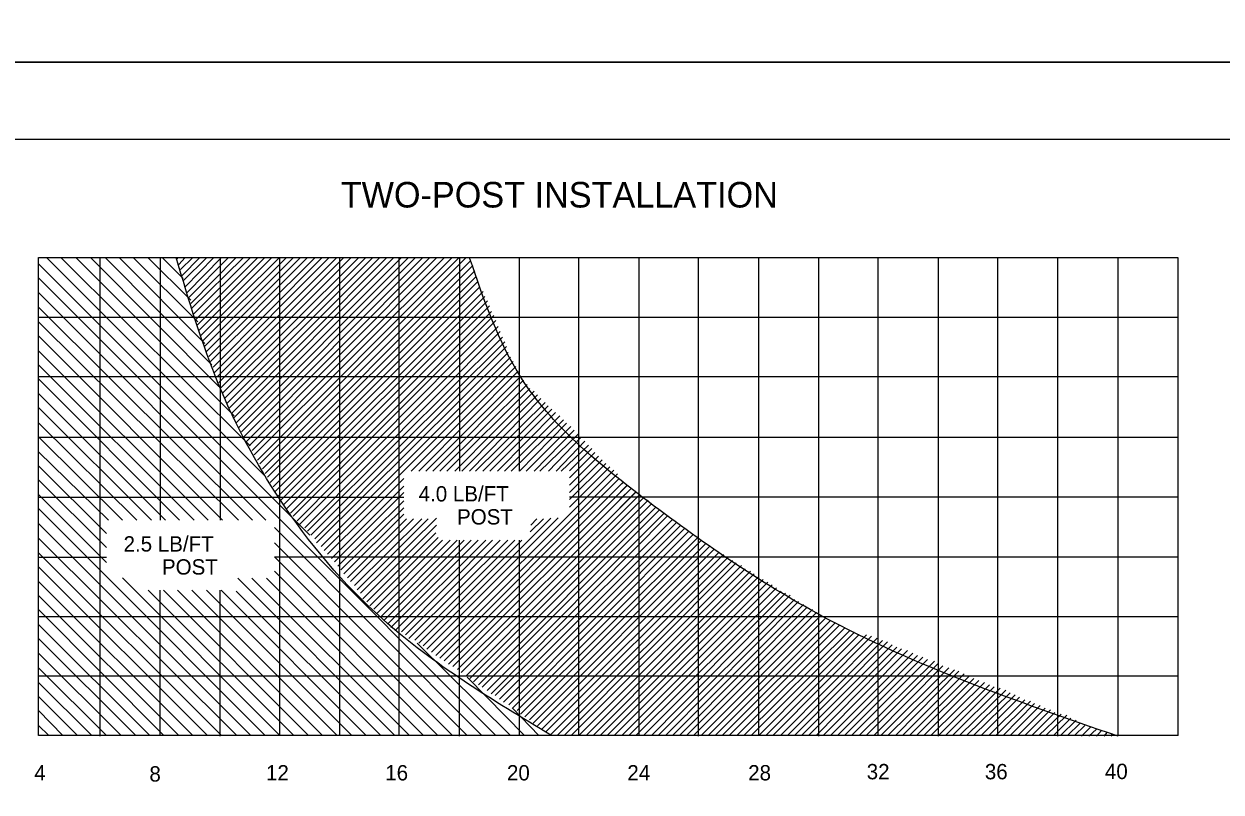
# Model space of a CAD drawing. Extents: x 644358 to 648627, y 294594 to 295782.
# Drawn here: x 645520.7 to 645754.7, y 295045 to 295195.1 of the extents above; entities that cross this region are included whole.
import ezdxf

# ---------------------------------------------------------------- set-up
doc = ezdxf.new("R2010")
doc.units = 0
for name, color, linetype in [('1', 7, 'Continuous'), ('10', 7, 'Continuous'), ('2', 7, 'Continuous'), ('4', 7, 'Continuous'), ('PLT-BNDY', 7, 'Continuous')]:
    doc.layers.add(name, color=color, linetype=linetype)

msp = doc.modelspace()

# ---------------------------------------------------------------- linework, layer by layer
at = {"layer": '1'}
msp.add_line((645239.31, 295172.63), (646025.31, 295172.63), dxfattribs=at)
at = {"layer": '10'}
for p, q in [((645576.63, 295095.21), (645523.59, 295148.25)), ((645567.96, 295106.63), (645525.21, 295149.38)), ((645564.96, 295112.63), (645527.96, 295149.38)), ((645561.84, 295118.5), (645530.84, 295149.5)), ((645558.84, 295124.25), (645533.71, 295149.5)), ((645557.46, 295128.5), (645536.59, 295149.5)), ((645556.09, 295132.63), (645539.34, 295149.5)), ((645554.71, 295136.88), (645542.09, 295149.5)), ((645553.34, 295141.13), (645544.96, 295149.5)), ((645551.84, 295145.38), (645547.71, 295149.5)), ((645550.59, 295149.13), (645550.84, 295149.5)), ((645550.96, 295148.13), (645552.21, 295149.5)), ((645551.34, 295147.13), (645553.71, 295149.5)), ((645551.59, 295145.88), (645555.09, 295149.5)), ((645551.84, 295144.88), (645556.46, 295149.5)), ((645552.21, 295143.75), (645557.84, 295149.5)), ((645552.59, 295142.63), (645559.34, 295149.5)), ((645552.96, 295141.63), (645560.71, 295149.5)), ((645553.34, 295140.5), (645562.21, 295149.5)), ((645553.46, 295139.5), (645563.59, 295149.38)), ((645553.84, 295138.38), (645564.96, 295149.38)), ((645554.21, 295137.25), (645566.34, 295149.38)), ((645554.59, 295136.25), (645567.71, 295149.38)), ((645554.84, 295135.13), (645569.09, 295149.38)), ((645555.21, 295134.13), (645570.59, 295149.38)), ((645555.59, 295133.13), (645571.96, 295149.38)), ((645556.09, 295132.13), (645573.34, 295149.38)), ((645556.34, 295131), (645574.71, 295149.38)), ((645556.84, 295130.13), (645576.09, 295149.38)), ((645557.21, 295129.13), (645577.59, 295149.38)), ((645557.71, 295128), (645578.96, 295149.38)), ((645557.96, 295127), (645580.34, 295149.38)), ((645558.46, 295126.13), (645581.84, 295149.38)), ((645558.84, 295125), (645583.21, 295149.38)), ((645559.21, 295124), (645584.59, 295149.38)), ((645559.59, 295123), (645586.09, 295149.38)), ((645559.96, 295122), (645587.46, 295149.38)), ((645560.46, 295121), (645588.84, 295149.38)), ((645560.84, 295120), (645590.21, 295149.38)), ((645561.21, 295118.88), (645591.59, 295149.38)), ((645561.59, 295118), (645592.96, 295149.38)), ((645562.21, 295117.13), (645594.46, 295149.38)), ((645562.59, 295116.13), (645595.84, 295149.38)), ((645563.21, 295115.38), (645597.21, 295149.38)), ((645563.71, 295114.38), (645598.59, 295149.38)), ((645564.21, 295113.5), (645599.96, 295149.38)), ((645564.71, 295112.63), (645601.34, 295149.38)), ((645565.34, 295111.75), (645602.84, 295149.38)), ((645565.71, 295110.88), (645604.34, 295149.38)), ((645566.34, 295109.88), (645605.71, 295149.38)), ((645566.84, 295109.13), (645607.09, 295149.38)), ((645567.34, 295108.13), (645608.09, 295148.88)), ((645567.84, 295107.25), (645608.46, 295147.88)), ((645570.71, 295098.31), (645523.59, 295145.5)), ((645568.34, 295106.5), (645608.84, 295146.88)), ((645568.84, 295105.5), (645609.09, 295145.75)), ((645569.46, 295104.63), (645609.46, 295144.75)), ((645569.84, 295103.75), (645609.84, 295143.75)), ((645568, 295098.09), (645523.59, 295142.63)), ((645570.46, 295102.88), (645610.51, 295142.8)), ((645570.96, 295102), (645610.81, 295141.85)), ((645571.46, 295101.13), (645611.33, 295140.99)), ((645565.37, 295098.09), (645523.59, 295139.75)), ((645572.09, 295100.38), (645611.71, 295140)), ((645572.84, 295099.5), (645612.13, 295138.92)), ((645562.63, 295098.09), (645523.59, 295136.88)), ((645573.34, 295098.88), (645612.56, 295138.1)), ((645574.09, 295098), (645612.97, 295137.14)), ((645574.59, 295097.25), (645613.42, 295135.96)), ((645559.5, 295098.09), (645523.59, 295134.13)), ((645575.6, 295096.64), (645613.83, 295135)), ((645594.09, 295113.82), (645614.25, 295133.91)), ((645556.75, 295098.09), (645523.59, 295131.25)), ((645577.57, 295094.49), (645615.03, 295132.08)), ((645594.09, 295112.44), (645614.72, 295133)), ((645577.93, 295093.69), (645615.34, 295130.88)), ((645578.83, 295093), (645615.84, 295130)), ((645579.41, 295092.2), (645616.34, 295129.13)), ((645554, 295098.09), (645523.59, 295128.5)), ((645596.39, 295107.68), (645616.84, 295128.13)), ((645597.91, 295107.68), (645617.34, 295127.25)), ((645551.12, 295098.09), (645523.59, 295125.75)), ((645599.27, 295107.68), (645617.84, 295126.25)), ((645600.66, 295107.68), (645618.34, 295125.5)), ((645602, 295107.68), (645619.09, 295124.63)), ((645548.37, 295098.09), (645523.59, 295122.88)), ((645603.39, 295107.68), (645619.59, 295123.88)), ((645604.91, 295107.68), (645620.43, 295123.35)), ((645606.29, 295107.68), (645621.09, 295122.64)), ((645607.81, 295107.68), (645621.72, 295121.89)), ((645545.62, 295098.09), (645523.59, 295120.13)), ((645608.99, 295107.68), (645622.6, 295121.13)), ((645610.39, 295107.68), (645623.19, 295120.48)), ((645611.77, 295107.68), (645623.93, 295119.85)), ((645542.75, 295098.09), (645523.59, 295117.13)), ((645613.3, 295107.68), (645624.59, 295119.14)), ((645614.64, 295107.68), (645625.45, 295118.49)), ((645615.98, 295107.68), (645626.21, 295117.74)), ((645617.56, 295107.68), (645626.79, 295117.1)), ((645618.89, 295107.68), (645627.61, 295116.4)), ((645620.44, 295107.68), (645628.28, 295115.72)), ((645621.58, 295107.68), (645629.03, 295114.92)), ((645540, 295098.09), (645523.59, 295114.38)), ((645576.17, 295095.96), (645594.09, 295113.82)), ((645576.8, 295095.22), (645594.09, 295112.44)), ((645623.22, 295107.68), (645629.63, 295114.32)), ((645624.73, 295107.68), (645630.35, 295113.54)), ((645625.71, 295107.68), (645631.04, 295112.8)), ((645537.24, 295098.09), (645523.59, 295111.5)), ((645627.35, 295107.77), (645631.71, 295112.13)), ((645627.35, 295106.38), (645632.32, 295111.35)), ((645627.35, 295104.97), (645633.02, 295110.64)), ((645536.84, 295095.5), (645523.59, 295108.75)), ((645600.41, 295072.32), (645636, 295107.91)), ((645627.35, 295103.56), (645633.73, 295109.94)), ((645627.35, 295102.14), (645634.44, 295109.23)), ((645627.35, 295100.64), (645635.24, 295108.53)), ((645536.84, 295092.75), (645523.59, 295106)), ((645580.08, 295091.49), (645594.98, 295106.24)), ((645602, 295071.17), (645637.02, 295106.18)), ((645602.86, 295070.65), (645637.86, 295105.52)), ((645629.21, 295099.63), (645636.76, 295107.18)), ((645637.21, 295104.88), (645637.84, 295105.5)), ((645536.84, 295089.87), (645523.59, 295103.13)), ((645580.86, 295090.65), (645594.98, 295104.77)), ((645581.43, 295089.97), (645594.98, 295103.52)), ((645603.69, 295069.98), (645638.63, 295104.92)), ((645604.57, 295069.49), (645639.4, 295104.31)), ((645605.49, 295068.9), (645640.32, 295103.61)), ((645606.2, 295068.36), (645641.02, 295103.06)), ((645637.12, 295099.18), (645641.09, 295103.13)), ((645637.21, 295102.13), (645639.46, 295104.38)), ((645637.21, 295100.52), (645640.34, 295103.63)), ((645637.35, 295103.64), (645638.71, 295105)), ((645582.1, 295089.14), (645594.98, 295101.89)), ((645607.09, 295067.63), (645641.84, 295102.5)), ((645607.85, 295067.14), (645642.71, 295102)), ((645608.62, 295066.54), (645643.46, 295101.38)), ((645535.59, 295088.34), (645523.59, 295100.38)), ((645582.65, 295088.43), (645594.98, 295100.56)), ((645583.22, 295087.63), (645594.98, 295099.29)), ((645583.94, 295086.86), (645595.5, 295098.41)), ((645584.57, 295086.11), (645596.87, 295098.41)), ((645585.32, 295085.36), (645598.47, 295098.41)), ((645585.84, 295084.51), (645599.75, 295098.41)), ((645586.53, 295083.82), (645601.34, 295098.5)), ((645598.78, 295073.57), (645623.7, 295098.49)), ((645599.49, 295072.91), (645625.13, 295098.55)), ((645601.24, 295071.66), (645629.21, 295099.63)), ((645609.54, 295065.96), (645644.21, 295100.63)), ((645610.3, 295065.47), (645644.96, 295100.13)), ((645611.25, 295064.8), (645645.84, 295099.5)), ((645612.02, 295064.19), (645646.59, 295099)), ((645619.67, 295095.84), (645622.25, 295098.41)), ((645619.77, 295097.16), (645620.98, 295098.41)), ((645535.59, 295085.5), (645523.59, 295097.5)), ((645610.21, 295056), (645569.66, 295096.69)), ((645612.96, 295056), (645570.71, 295098.31)), ((645586.96, 295082.75), (645601.34, 295097.13)), ((645612.81, 295063.85), (645647.46, 295098.25)), ((645613.7, 295063.12), (645648.21, 295097.63)), ((645614.47, 295062.52), (645649.09, 295097.13)), ((645615.47, 295062.02), (645649.84, 295096.5)), ((645562.34, 295056), (645523.59, 295094.63)), ((645607.34, 295056), (645569.66, 295093.68)), ((645587.71, 295082.13), (645601.21, 295095.63)), ((645588.34, 295081.38), (645601.68, 295094.72)), ((645589.09, 295080.75), (645602.53, 295094.2)), ((645589.71, 295079.88), (645604.03, 295094.2)), ((645590.46, 295079.25), (645605.4, 295094.2)), ((645591.09, 295078.5), (645606.78, 295094.2)), ((645591.84, 295077.88), (645608.15, 295094.2)), ((645592.46, 295077.13), (645609.53, 295094.2)), ((645593.34, 295076.63), (645611.02, 295094.2)), ((645594.53, 295076.32), (645612.29, 295094.2)), ((645595.3, 295075.71), (645613.78, 295094.2)), ((645595.93, 295074.97), (645615.27, 295094.2)), ((645597.1, 295074.64), (645616.65, 295094.2)), ((645597.92, 295074.09), (645618.03, 295094.2)), ((645616.16, 295061.33), (645650.71, 295096)), ((645617.13, 295060.92), (645651.46, 295095.25)), ((645617.79, 295060.21), (645652.34, 295094.63)), ((645618.62, 295059.66), (645653.09, 295094.13)), ((645559.34, 295056), (645523.59, 295091.75)), ((645619.52, 295059.06), (645653.96, 295093.5)), ((645620.27, 295058.44), (645654.84, 295093.13)), ((645621.1, 295057.89), (645655.71, 295092.5)), ((645621.97, 295057.26), (645656.59, 295091.88)), ((645622.71, 295056.75), (645657.46, 295091.38)), ((645556.59, 295056), (645523.59, 295089)), ((645604.46, 295056), (645569.66, 295090.93)), ((645623.71, 295056.25), (645658.34, 295090.88)), ((645624.96, 295056), (645659.21, 295090.25)), ((645626.34, 295056), (645659.96, 295089.75)), ((645627.71, 295056), (645660.96, 295089.25)), ((645567.84, 295056), (645535.59, 295088.34)), ((645570.71, 295056), (645539.99, 295086.83)), ((645593.21, 295056), (645562.54, 295086.8)), ((645596.09, 295056), (645565.29, 295086.8)), ((645598.84, 295056), (645568.16, 295086.8)), ((645601.59, 295056), (645569.66, 295088.17)), ((645629.21, 295056), (645661.71, 295088.63)), ((645630.59, 295056), (645662.71, 295088.13)), ((645631.96, 295056), (645663.46, 295087.63)), ((645633.34, 295056), (645664.34, 295087.13)), ((645553.71, 295056), (645523.59, 295086.13)), ((645565.09, 295056), (645534.49, 295086.6)), ((645573.46, 295056), (645545.01, 295084.46)), ((645576.34, 295056), (645548.01, 295084.46)), ((645579.09, 295056), (645550.76, 295084.46)), ((645581.96, 295056), (645553.51, 295084.46)), ((645584.84, 295056), (645556.38, 295084.46)), ((645587.59, 295056), (645559.26, 295084.46)), ((645634.71, 295056), (645665.21, 295086.5)), ((645636.09, 295056), (645666.09, 295086)), ((645637.59, 295056), (645666.96, 295085.5)), ((645638.96, 295056), (645667.84, 295084.88)), ((645550.96, 295056), (645523.59, 295083.38)), ((645590.46, 295056), (645562.21, 295084.25)), ((645640.34, 295056), (645668.71, 295084.25)), ((645641.84, 295056), (645669.59, 295083.88)), ((645643.41, 295056.01), (645670.51, 295083.48)), ((645644.71, 295056), (645671.34, 295082.63)), ((645646.09, 295056), (645672.09, 295082.25)), ((645548.09, 295056), (645523.59, 295080.63)), ((645647.46, 295056), (645673.09, 295081.63)), ((645648.84, 295056), (645673.84, 295081.13)), ((645650.21, 295056), (645674.84, 295080.63)), ((645651.59, 295056), (645675.59, 295080)), ((645545.34, 295056), (645523.59, 295077.75)), ((645653.09, 295056), (645676.46, 295079.5)), ((645654.46, 295056), (645677.46, 295079)), ((645655.84, 295056), (645678.34, 295078.5)), ((645657.21, 295056), (645679.34, 295078.13)), ((645658.59, 295056), (645680.21, 295077.63)), ((645542.59, 295056), (645523.59, 295075)), ((645660.09, 295056), (645681.21, 295077.13)), ((645661.46, 295056), (645682.21, 295076.63)), ((645662.84, 295056), (645683.09, 295076.25)), ((645664.34, 295056), (645683.96, 295075.75)), ((645665.71, 295056), (645685.43, 295075.72)), ((645667.09, 295056), (645686.38, 295075.43)), ((645668.59, 295056), (645687.47, 295075.02)), ((645615.84, 295056), (645597.56, 295074.1)), ((645669.96, 295056), (645688.56, 295074.6)), ((645671.34, 295056), (645689.52, 295074.31)), ((645672.71, 295056), (645690.43, 295073.72)), ((645674.09, 295056), (645691.37, 295073.29)), ((645675.59, 295056), (645692.28, 295072.96)), ((645676.96, 295056), (645693.45, 295072.63)), ((645539.71, 295056), (645523.59, 295072.13)), ((645678.34, 295056), (645694.47, 295072.14)), ((645679.71, 295056), (645695.39, 295071.68)), ((645681.09, 295056), (645696.45, 295071.36)), ((645682.46, 295056), (645697.32, 295070.86)), ((645683.96, 295056), (645698.67, 295070.58)), ((645536.84, 295056), (645523.59, 295069.25)), ((645685.34, 295056), (645699.51, 295070.18)), ((645686.84, 295056), (645700.33, 295069.64)), ((645688.21, 295056), (645701.47, 295069.26)), ((645689.59, 295056), (645702.58, 295068.85)), ((645691.09, 295056), (645703.43, 295068.62)), ((645692.46, 295056), (645704.53, 295068.07)), ((645533.96, 295056), (645523.59, 295066.38)), ((645618.59, 295056), (645607.38, 295067.42)), ((645693.84, 295056), (645705.45, 295067.61)), ((645695.21, 295056), (645706.4, 295067.19)), ((645696.59, 295056), (645707.38, 295066.8)), ((645697.96, 295056), (645708.48, 295066.39)), ((645699.46, 295056), (645709.42, 295065.96)), ((645531.21, 295056), (645523.59, 295063.63)), ((645700.84, 295056), (645710.37, 295065.53)), ((645702.21, 295056), (645711.51, 295065.3)), ((645703.59, 295056), (645712.62, 295064.89)), ((645704.96, 295056), (645713.49, 295064.38)), ((645706.34, 295056), (645714.44, 295063.96)), ((645707.84, 295056), (645715.33, 295063.5)), ((645621.34, 295056), (645616.19, 295061.36)), ((645709.34, 295056), (645716.34, 295063.01)), ((645710.71, 295056), (645717.44, 295062.73)), ((645712.09, 295056), (645718.23, 295062.3)), ((645713.46, 295056), (645719.34, 295061.88)), ((645714.96, 295056), (645720.35, 295061.39)), ((645716.34, 295056), (645721.38, 295061.04)), ((645528.34, 295056), (645523.59, 295060.88)), ((645717.71, 295056), (645722.22, 295060.51)), ((645719.09, 295056), (645723.44, 295060.21)), ((645720.46, 295056), (645724.59, 295059.97)), ((645721.96, 295056), (645725.35, 295059.39)), ((645723.34, 295056), (645726.38, 295059.04)), ((645525.59, 295056), (645523.59, 295058)), ((645724.71, 295056), (645727.09, 295058.38)), ((645726.09, 295056), (645728.09, 295058)), ((645727.46, 295055.88), (645729.21, 295057.63)), ((645728.84, 295055.88), (645730.34, 295057.25)), ((645730.34, 295055.88), (645731.34, 295057)), ((645731.84, 295055.88), (645732.46, 295056.63)), ((645733.21, 295055.88), (645733.46, 295056.25)), ((645734.59, 295055.88), (645734.59, 295055.88))]:
    msp.add_line(p, q, dxfattribs=at)
at = {"layer": '2'}
for p, q in [((645523.59, 295056), (645523.59, 295149.5)), ((645746.34, 295149.38), (645523.59, 295149.38)), ((645535.59, 295090.88), (645535.59, 295149.38)), ((645547.34, 295149.38), (645547.34, 295098.09)), ((645559.09, 295149.38), (645559.09, 295098.09)), ((645570.71, 295090.88), (645570.71, 295149.38)), ((645582.46, 295056), (645582.46, 295149.38)), ((645594.09, 295102.63), (645594.09, 295149.38)), ((645605.84, 295149.38), (645605.84, 295107.68)), ((645617.59, 295107.68), (645617.59, 295149.38)), ((645629.21, 295102.63), (645629.21, 295149.38)), ((645640.96, 295056), (645640.96, 295149.38)), ((645652.59, 295055.88), (645652.59, 295149.38)), ((645664.34, 295056), (645664.34, 295149.38)), ((645676.09, 295055.88), (645676.09, 295149.38)), ((645687.71, 295056), (645687.71, 295149.38)), ((645699.46, 295055.88), (645699.46, 295149.38)), ((645711.09, 295056), (645711.09, 295149.38)), ((645722.84, 295055.88), (645722.84, 295149.38)), ((645734.59, 295056), (645734.59, 295149.38)), ((645746.34, 295056), (645746.34, 295149.38)), ((645746.34, 295137.75), (645523.59, 295137.75)), ((645746.34, 295126.13), (645523.59, 295126.13)), ((645746.34, 295114.25), (645523.59, 295114.25)), ((645523.59, 295102.63), (645594.98, 295102.63)), ((645594.09, 295056), (645594.09, 295102.63)), ((645649.96, 295102.63), (645627.35, 295102.63)), ((645629.21, 295056), (645629.21, 295102.63)), ((645746.34, 295102.63), (645649.96, 295102.63)), ((645605.84, 295055.88), (645605.84, 295094.2)), ((645617.59, 295056), (645617.59, 295094.2)), ((645523.59, 295090.88), (645536.84, 295090.88)), ((645535.59, 295055.88), (645535.59, 295090.88)), ((645593.46, 295090.88), (645569.66, 295090.88)), ((645570.71, 295056), (645570.71, 295090.88)), ((645746.34, 295090.88), (645593.46, 295090.88)), ((645547.34, 295056), (645547.34, 295084.46)), ((645559.09, 295055.88), (645559.09, 295084.46)), ((645746.34, 295079.25), (645523.59, 295079.25)), ((645746.34, 295067.63), (645523.59, 295067.63)), ((645746.34, 295056), (645523.59, 295056))]:
    msp.add_line(p, q, dxfattribs=at)
at = {"layer": '4'}
for points in [[(645623.84, 295056), (645590.84, 295078.75), (645570.71, 295102.25), (645558.84, 295124.5), (645550.46, 295149.5)], [(645734.59, 295055.88), (645676.71, 295079.38), (645641.59, 295102.63), (645617.96, 295125.88), (645607.84, 295149.38)]]:
    msp.add_spline(points, degree=3, dxfattribs=at)
at = {"layer": 'PLT-BNDY'}
for points in [[(645199.31, 295781.63), (646040.31, 295781.63), (646040.31, 295187.63), (645199.31, 295187.63)], [(645199.31, 295187.63), (646040.31, 295187.63), (646040.31, 294593.63), (645199.31, 294593.63)]]:
    msp.add_lwpolyline(points, close=True, dxfattribs=at)

# ---------------------------------------------------------------- texts
at = {"layer": '2'}
for s, height, p in [('TWO-POST INSTALLATION', 5, (645582.64, 295159.24)), ('4', 3, (645522.74, 295047.24)), ('8', 3, (645545.24, 295047.02)), ('12', 3, (645568.03, 295047.24)), ('16', 3, (645591.34, 295047.24)), ('20', 3, (645615.13, 295047.24)), ('24', 3, (645638.66, 295047.24)), ('28', 3, (645662.28, 295047.24)), ('32', 3, (645685.45, 295047.46)), ('36', 3, (645708.54, 295047.46)), ('40', 3, (645732.01, 295047.51))]:
    msp.add_text(s, height=height, dxfattribs=at).set_placement(p)
at = {"layer": '4'}
for s, p in [('4.0 LB/FT', (645597.87, 295101.77)), ('POST', (645605.37, 295097.27)), ('2.5 LB/FT', (645540.19, 295091.98)), ('POST', (645547.69, 295087.48))]:
    msp.add_text(s, height=3, dxfattribs=at).set_placement(p)

doc.saveas('drawing.dxf')
